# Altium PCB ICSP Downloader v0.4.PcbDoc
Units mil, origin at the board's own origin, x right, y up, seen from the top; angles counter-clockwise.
Board outline 700 x 1900 mil, 2 copper layers (Top Layer, Bottom Layer); 12 components, 15 nets, 64 pads, 0 vias.
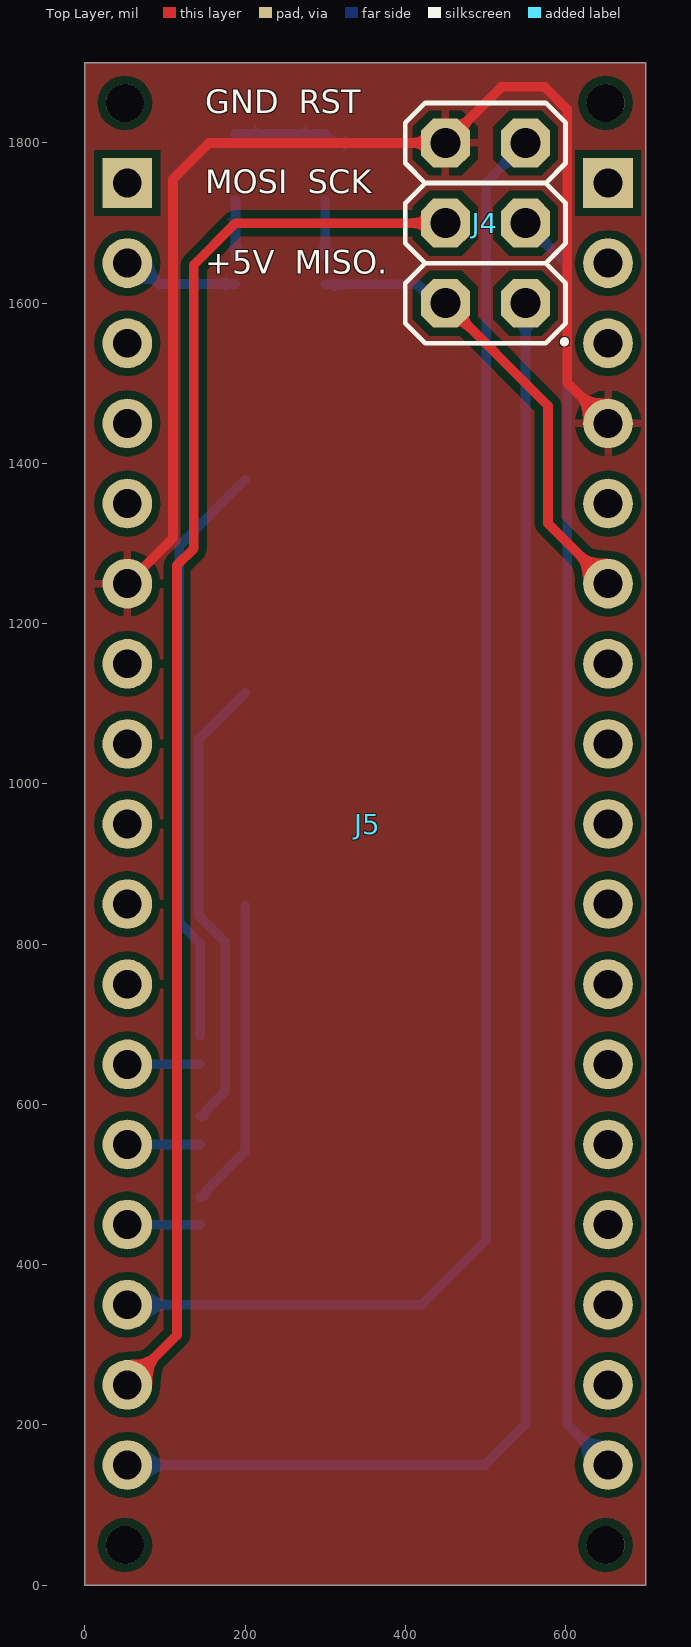
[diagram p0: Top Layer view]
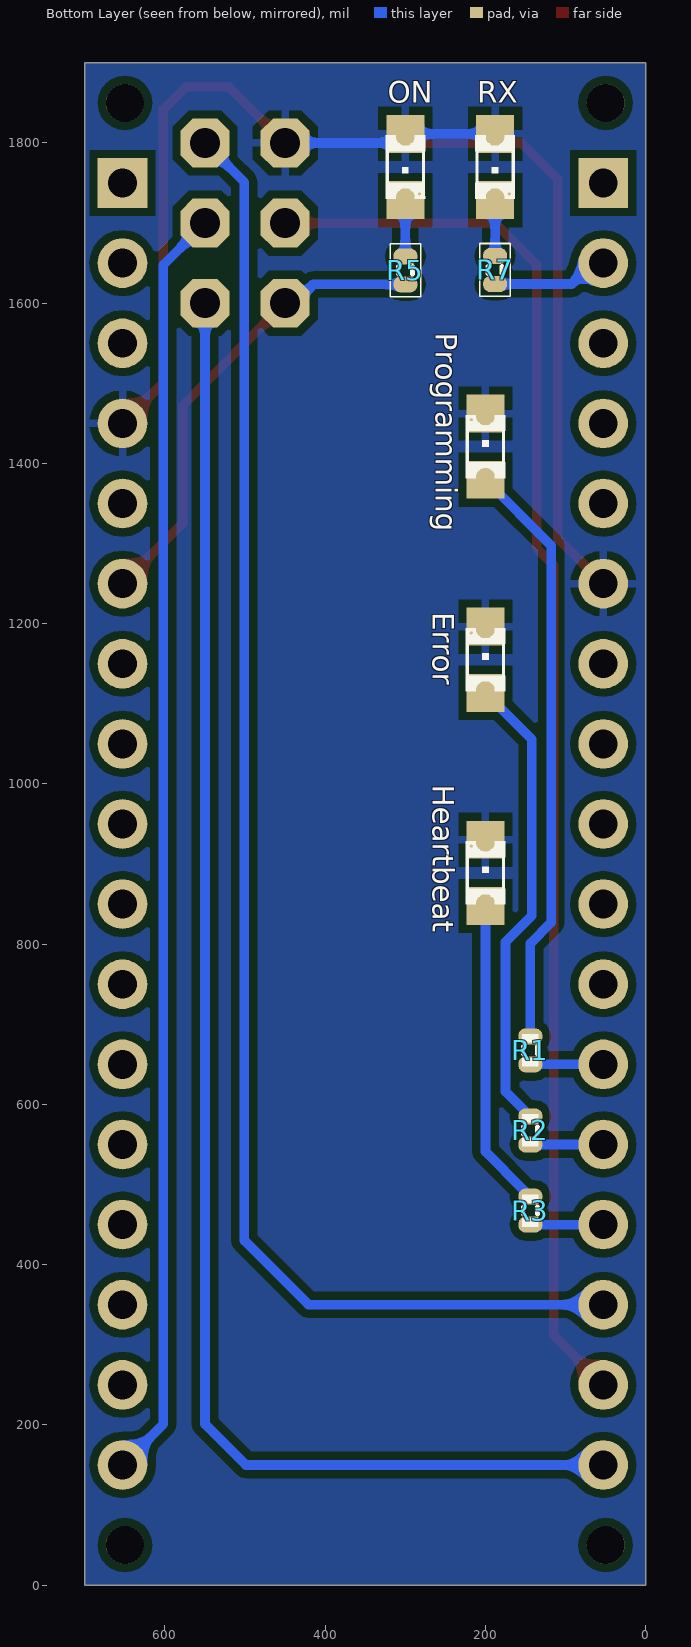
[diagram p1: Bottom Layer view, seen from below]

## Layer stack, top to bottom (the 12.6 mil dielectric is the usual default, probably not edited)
Top Solder: solder mask 0.4, Solder Resist, Dk 3.5
Top Layer: signal copper 1.4
Dielectric 1: dielectric 12.6, FR-4, Dk 4.8
Bottom Layer: signal copper 1.4
Bottom Solder: solder mask 0.4, Solder Resist, Dk 3.5

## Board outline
0,0 0,1900 700,1900 700,0

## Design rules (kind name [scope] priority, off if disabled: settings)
Clearance [All] p1: gap=10 ignorepadtopadclearanceinfootprint=TRUE
PolygonConnect [All] p1: connectstyle=Relief reliefconductorwidth=10 reliefentries=4 polygonreliefangle="90 Angle" airgapwidth=10
RoutingVias [All] p1: holewidth=28 width=50 viastyle="Through Hole" minholewidth=28 minwidth=50 maxholewidth=28 maxwidth=50
SolderMaskExpansion [All] p1: expansion=4
UnRoutedNet [All] p1: checkbadconnections=TRUE
Width [All] p1: maxlimit=16 minlimit=5 preferedwidth=12
29 further rules are at their usual default settings.

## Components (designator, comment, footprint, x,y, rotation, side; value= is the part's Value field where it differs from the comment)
Error "LED2" LED_0805#1 200,1155 r180 bottom
Heartbeat "LED2" LED_0805#1 200,889 r180 bottom
J4 "ICSP" ICSP 386,1536 r0 top locked
J5 "17Pin*2" 17Pin*2 53,1750 r0 top locked
ON "LED2" LED_0805#2 300,1770 r0 bottom
Programming "LED2" LED_0805#1 200,1421 r180 bottom
R1 "Res3" R0402 167,632.5 r180 bottom value=1K
R2 "Res3" R0402 167,532.5 r180 bottom value=1K
R3 "Res3" R0402 167,432.5 r180 bottom value=1K
R5 "Res3" R0402 277,1676 r0 bottom value=1K
R7 "Res3" R0402 211,1606.5 r180 bottom value=1K
RX "LED2" LED_0805#2 188,1770 r0 bottom

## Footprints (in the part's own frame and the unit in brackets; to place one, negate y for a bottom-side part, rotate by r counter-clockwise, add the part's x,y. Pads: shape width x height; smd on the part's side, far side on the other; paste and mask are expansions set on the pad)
17Pin*2 [mil]
  rect 62x62 / inner round 57.28 / far side rect 62x62 hole 36: 1(0,0) 34(600,0)
  round 62 hole 36: 2(0,-100) 3(0,-200) 4(0,-300) 5(0,-400) 6(0,-500) 7(0,-600) 8(0,-700) 9(0,-800) 10(0,-900) 11(0,-1000) 12(0,-1100) 13(0,-1200) 14(0,-1300) 15(0,-1400) 16(0,-1500) 17(0,-1600) 18(600,-1600) 19(600,-1500) 20(600,-1400) 21(600,-1300) 22(600,-1200) 23(600,-1100) 24(600,-1000) 25(600,-900) 26(600,-800) 27(600,-700) 28(600,-600) 29(600,-500) 30(600,-400) 31(600,-300) 32(600,-200) 33(600,-100)
ICSP [mil]
  oct 61.02x61.02 / inner round 56.38 / far side oct 61.02x61.02 hole 37.4: 1(164,64) 2(64,64) 3(164,164) 4(64,164) 5(164,264) 6(64,264)
  silkscreen extent 14,14 214,314
LED_0805#1 [mil] "CHIPLED_0805"
  rect 47.24x47.24 smd: 1(0,-41.34) 2(0,41.34)
  silkscreen extent -25,-39 25,39
LED_0805#2 [mil] "CHIPLED_0805"
  rect 47.24x47.24 smd: 1(0,41.34) 2(0,-41.34)
  silkscreen extent -25,-39 25,39
R0402 [mil]
  rrect90% 30x20 smd: 1(23,52.5) 2(23,17.5)
  silkscreen extent 13,15 33,55

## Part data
Error Heartbeat ON Programming RX: "Typical RED, GREEN, YELLOW, AMBER GaAs LED"
J4: "2.54"
J5: "Arduino Micro"
R1 R2 R3 R5 R7: "Resistor"

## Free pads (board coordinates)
  round 47.24 hole 47.24 unplated: MH1(50,50) MH2(650,50) MH3(50,1850) MH4(650,1850)

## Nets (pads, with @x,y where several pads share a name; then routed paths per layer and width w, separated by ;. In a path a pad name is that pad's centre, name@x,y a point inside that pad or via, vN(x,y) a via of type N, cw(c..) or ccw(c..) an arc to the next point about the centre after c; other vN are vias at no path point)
+5V: J4.2 J5.29 R5.1 | length 593.8
  Top Layer w12: J4.2 578,1472 578,1325 J5.29
  Bottom Layer w12: R5.1 414.76,1623.5 438.26,1600 J4.2
D7: J5.12 R1.2 | length 91
  Bottom Layer w12: J5.12 R1.2
D8: J5.13 R2.2 | length 91
  Bottom Layer w12: J5.13 R2.2
D9: J5.14 R3.2 | length 91
  Bottom Layer w12: J5.14 R3.2
GND: Error.2 Heartbeat.2 J4.6 J5.6 J5.31 ON.2 Programming.2 RX.2 | length 1759.7
  Top Layer w10: J5.6 J5.6@56.98,1253.98
  Top Layer w12: J5.6@56.98,1253.98 110,1307 110,1755 155,1800 J4.6 520,1870 574,1870 602,1842 602,1501 J5.31
  Bottom Layer w12: RX.2 ON.2 311.34,1800 J4.6
MISO: J4.1 J5.17 | length 1917.1
  Bottom Layer w12: J5.17 499,150 550,201 J4.1
MOSI: J4.4 J5.16 | length 1767.9
  Top Layer w12: J5.16 115,312 115,1273 136,1294 136,1648 188,1700 J4.4
NetError_1: Error.1 R2.1 | length 581.2
  Bottom Layer w12: R2.1 147.38,585 151.15,588.77 151.15,592.15 175,616 175,802.79 142,835.79 142,1055.66 Error.1
NetHeartbeat_1: Heartbeat.1 R3.1 | length 387.8
  Bottom Layer w12: R3.1 147.38,485 151.15,488.77 151.15,492.15 200,541 Heartbeat.1
NetJ5_2: J5.2 R7.2 | length 145.8
  Bottom Layer w12: J5.2 66.53,1650 92.53,1624 R7.2
NetON_1: ON.1 R5.2 | length 70.2
  Bottom Layer w12: R5.2 ON.1
NetProgramming_1: Programming.1 R1.1 | length 739.4
  Bottom Layer w12: R1.1 144,800.79 118,826.79 118,1297.66 Programming.1
NetR7_1: R7.1 RX.1 | length 69.7
  Bottom Layer w12: R7.1 RX.1
RESET: J4.5 J5.15 | length 1871.4
  Bottom Layer w12: J5.15 421,350 501,430 501,1751 J4.5
SCK: J4.3 J5.18 | length 1592.7
  Bottom Layer w12: J4.3 602,1648 602,201 J5.18
pads on no net: J5.1 J5.3 J5.4 J5.5 J5.7 J5.8 J5.9 J5.10 J5.11 J5.19 J5.20 J5.21 J5.22 J5.23 J5.24 J5.25 J5.26 J5.27 J5.28 J5.30 J5.32 J5.33 J5.34

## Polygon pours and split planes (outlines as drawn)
GND on Bottom Layer "Bottom Layer-GND" (solid, remove dead copper, pour order 10): 0,1900 0,0 700,0 700,1900
GND on Top Layer "Top Layer-GND" (solid, remove dead copper, pour order 12): 0,1900 0,0 700,0 700,1900

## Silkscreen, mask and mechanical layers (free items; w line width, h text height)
Top Overlay:
  text "GND  RST /  / MOSI  SCK /  / +5V  MISO. /  /                                    •" at 150,1527 h50
Top Solder:
  lines w5: 140,1590 394,1590 394,1805 140,1805 140,1590
Bottom Solder:
  drawing of 660 lines, arcs and shapes, not listed
  text "ICSP downloader for Arduino bootloader" at 369,1440 h62 r90
  text "22-18" at 417,33 h60
Mechanical 1:
  the board outline again, w2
